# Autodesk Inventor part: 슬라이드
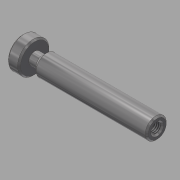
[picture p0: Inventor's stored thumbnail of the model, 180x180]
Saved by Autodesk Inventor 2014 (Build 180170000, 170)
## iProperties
Created: 2015-12
Part Number: 슬라이드
Document SubType Name: Modeling
Designer: mdu
Density: 7.87 g/cm^3
Material: 스테인레스 스틸
Appearance: 반연마
Mass: 111.518 g
Surface Area: 49.8963 cm^2
Volume: 14.17 cm^3
Author: mdu
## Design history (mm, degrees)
sketch "스케치1"
  geometry: L1 (-45, 0)-(45, 0); L2 (-45, 0)-(-45, 10.5); L3 (-45, 10.5)-(-37, 10.5); L4 (-37, 10.5)-(-37, 4); L5 (-37, 4)-(-32, 4); L6 (-32, 4)-(-29, 7); L7 (-29, 7)-(45, 7); L8 (45, 7)-(45, 0); 2 further points
  constraints: 16 end point, 4 parallel, 2 perpendicular, 1 coincident, 1 horizontal, 1 midpoint
  dimensions: "d0" = 90 distance of L1.start L1.end; "d1" = 21 diameter of L3 L1; "d2" = 14 diameter of L7 L1; "d3" = 8 diameter of L5 L1; "d4" = 8 distance of L2.end L3.end; "d5" = 5 distance of L4.end L5.end; "d6" = 135 deg angle of L6 L5
revolve "회전1" sketch "스케치1" stored, may be unused: angle "d7" = 90 deg
chamfer "모따기1" distance "d8" = 1; stored, may be unused: second distance "d9" = 2, angle "d10" = 45 deg
hole "구멍1" diameter "d13" = 6.647; stored, may be unused: countersink angle "d17" = 90 deg, drill point angle "d19" = 118 deg; dims "d11" = 10, "d12" = 10, "d14" = 9, "d15" = 4, "d16" = 2, "d18" = 12
chamfer "모따기2" distance "d20" = 1; stored, may be unused: second distance "d21" = 2, angle "d22" = 45 deg
node "솔리드1"
